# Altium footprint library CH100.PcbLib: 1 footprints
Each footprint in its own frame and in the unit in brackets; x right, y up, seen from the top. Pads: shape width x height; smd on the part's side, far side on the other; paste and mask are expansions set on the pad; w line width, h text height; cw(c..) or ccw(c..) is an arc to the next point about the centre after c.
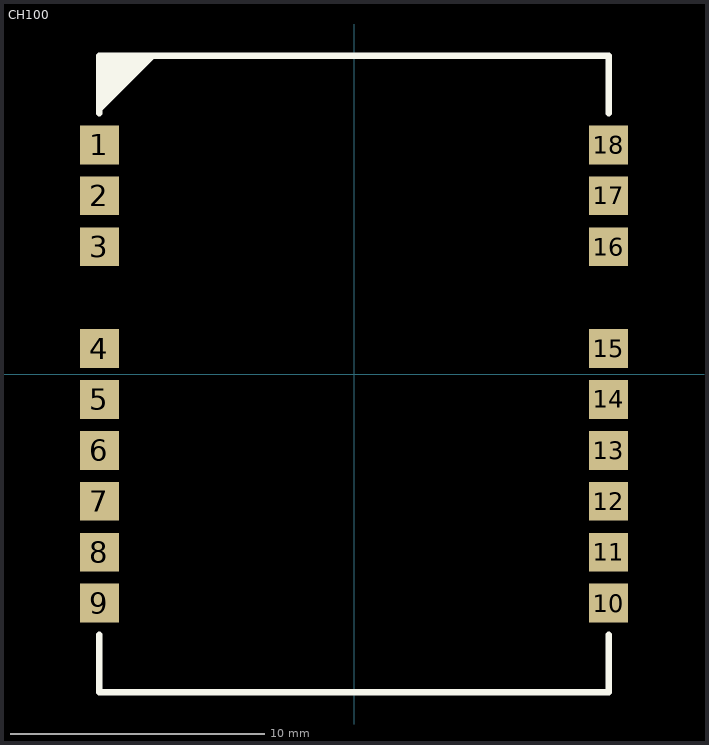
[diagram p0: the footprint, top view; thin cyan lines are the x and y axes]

## CH100 [mm]
pads (18):
  rect 1.524x1.524 smd: 1(-10,9) 2(-10,7) 3(-10,5) 4(-10,1) 5(-10,-1) 6(-10,-3) 7(-10,-5) 8(-10,-7) 9(-10,-9) 10(10,-9) 11(10,-7) 12(10,-5) 13(10,-3) 14(10,-1) 15(10,1) 16(10,5) 17(10,7) 18(10,9)
Top Overlay:
  region: -10,10.25 -7.75,12.5 -10,12.5
  lines w0.254: -10,-10.25 -10,-12.5 10,-12.5 10,-10.25 ; -10,10.25 -10,12.5 10,12.5 10,10.25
